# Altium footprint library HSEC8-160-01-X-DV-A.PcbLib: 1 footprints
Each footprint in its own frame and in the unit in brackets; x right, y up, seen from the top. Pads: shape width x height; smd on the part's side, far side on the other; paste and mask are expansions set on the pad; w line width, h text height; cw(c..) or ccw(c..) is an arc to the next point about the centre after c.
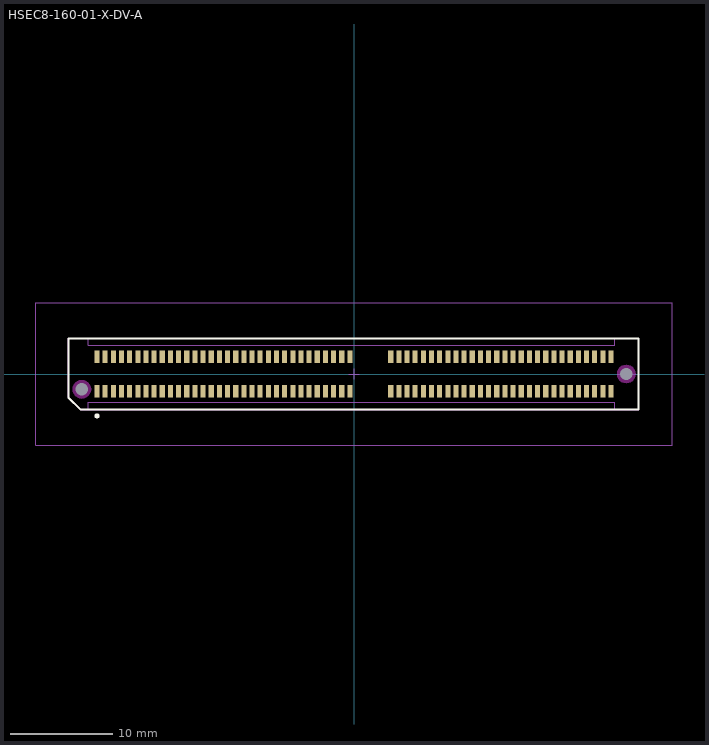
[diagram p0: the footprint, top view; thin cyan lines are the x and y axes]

## HSEC8-160-01-X-DV-A [mm] "0.80mm pitch, 80 pin, hi-speed micro edge card; w/alignment pins"
height 7.98
pads (122):
  rect 0.5x1.2 smd mask+0: 1(-25.2,-1.7) 2(-25.2,1.7) 3(-24.4,-1.7) 4(-24.4,1.7) 5(-23.6,-1.7) 6(-23.6,1.7) 7(-22.8,-1.7) 8(-22.8,1.7) 9(-22,-1.7) 10(-22,1.7) 11(-21.2,-1.7) 12(-21.2,1.7) 13(-20.4,-1.7) 14(-20.4,1.7) 15(-19.6,-1.7) 16(-19.6,1.7) 17(-18.8,-1.7) 18(-18.8,1.7) 19(-18,-1.7) 20(-18,1.7) 21(-17.2,-1.7) 22(-17.2,1.7) 23(-16.4,-1.7) 24(-16.4,1.7) 25(-15.6,-1.7) 26(-15.6,1.7) 27(-14.8,-1.7) 28(-14.8,1.7) 29(-14,-1.7) 30(-14,1.7) 31(-13.2,-1.7) 32(-13.2,1.7) 33(-12.4,-1.7) 34(-12.4,1.7) 35(-11.6,-1.7) 36(-11.6,1.7) 37(-10.8,-1.7) 38(-10.8,1.7) 39(-10,-1.7) 40(-10,1.7) 41(-9.2,-1.7) 42(-9.2,1.7) 43(-8.4,-1.7) 44(-8.4,1.7) 45(-7.6,-1.7) 46(-7.6,1.7) 47(-6.8,-1.7) 48(-6.8,1.7) 49(-6,-1.7) 50(-6,1.7) 51(-5.2,-1.7) 52(-5.2,1.7) 53(-4.4,-1.7) 54(-4.4,1.7) 55(-3.6,-1.7) 56(-3.6,1.7) 57(-2.8,-1.7) 58(-2.8,1.7) 59(-2,-1.7) 60(-2,1.7) 61(-1.2,-1.7) 62(-1.2,1.7) 63(-0.4,-1.7) 64(-0.4,1.7) 65(3.6,-1.7) 66(3.6,1.7) 67(4.4,-1.7) 68(4.4,1.7) 69(5.2,-1.7) 70(5.2,1.7) 71(6,-1.7) 72(6,1.7) 73(6.8,-1.7) 74(6.8,1.7) 75(7.6,-1.7) 76(7.6,1.7) 77(8.4,-1.7) 78(8.4,1.7) 79(9.2,-1.7) 80(9.2,1.7) 81(10,-1.7) 82(10,1.7) 83(10.8,-1.7) 84(10.8,1.7) 85(11.6,-1.7) 86(11.6,1.7) 87(12.4,-1.7) 88(12.4,1.7) 89(13.2,-1.7) 90(13.2,1.7) 91(14,-1.7) 92(14,1.7) 93(14.8,-1.7) 94(14.8,1.7) 95(15.6,-1.7) 96(15.6,1.7) 97(16.4,-1.7) 98(16.4,1.7) 99(17.2,-1.7) 100(17.2,1.7) 101(18,-1.7) 102(18,1.7) 103(18.8,-1.7) 104(18.8,1.7) 105(19.6,-1.7) 106(19.6,1.7) 107(20.4,-1.7) 108(20.4,1.7) 109(21.2,-1.7) 110(21.2,1.7) 111(22,-1.7) 112(22,1.7) 113(22.8,-1.7) 114(22.8,1.7) 115(23.6,-1.7) 116(23.6,1.7) 117(24.4,-1.7) 118(24.4,1.7) 119(25.2,-1.7) 120(25.2,1.7)
  round 1 hole 1.2 unplated mask+0: 121(-26.692,-1.5) 122(26.699,0)
Top Overlay:
  circle w0.25: c-25.2,-4.1 r0.125
  lines w0.2: -28,-2.3 -28,3.5 27.9,3.5 27.9,-3.5 -26.8,-3.5 -28,-2.3
Keep-Out Layer:
  pour cut-out: 27.607,0 27.576,0.235 27.485,0.454 27.341,0.642 27.153,0.786 26.934,0.877 26.699,0.908 26.464,0.877 26.245,0.786 26.057,0.642 25.913,0.454 25.822,0.235 25.791,0 25.822,-0.235 25.913,-0.454 26.057,-0.642 26.245,-0.786 26.464,-0.877 26.699,-0.908 26.934,-0.877 27.153,-0.786 27.341,-0.642 27.485,-0.454 27.576,-0.235
  pour cut-out: -25.784,-1.5 -25.815,-1.265 -25.906,-1.046 -26.05,-0.858 -26.238,-0.714 -26.457,-0.623 -26.692,-0.592 -26.927,-0.623 -27.146,-0.714 -27.334,-0.858 -27.478,-1.046 -27.569,-1.265 -27.6,-1.5 -27.569,-1.735 -27.478,-1.954 -27.334,-2.142 -27.146,-2.286 -26.927,-2.377 -26.692,-2.408 -26.457,-2.377 -26.238,-2.286 -26.05,-2.142 -25.906,-1.954 -25.815,-1.735
Mechanical 12:
  lines w0.001: -28,-2.3 -28,3.5 27.9,3.5 27.9,-3.5 -26.8,-3.5 -28,-2.3
Mechanical 13:
  lines w0.1: -31.2,-7 -31.2,7 31.2,7 31.2,-7 -31.2,-7 ; -28,-2.3 -28,3.499 -26.05,3.5 -26.05,2.8 25.549,2.8 25.549,3.5 27.9,3.5 27.9,-3.5 25.55,-3.5 25.55,-2.794 -26.05,-2.794 -26.05,-3.5 -26.8,-3.5 -28,-2.3
  text ".Designator" at 0.381,0.254 h1.52
Mechanical 15:
  lines w0.05: -0.5,0 0.5,0 ; 0,-0.5 0,0.5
